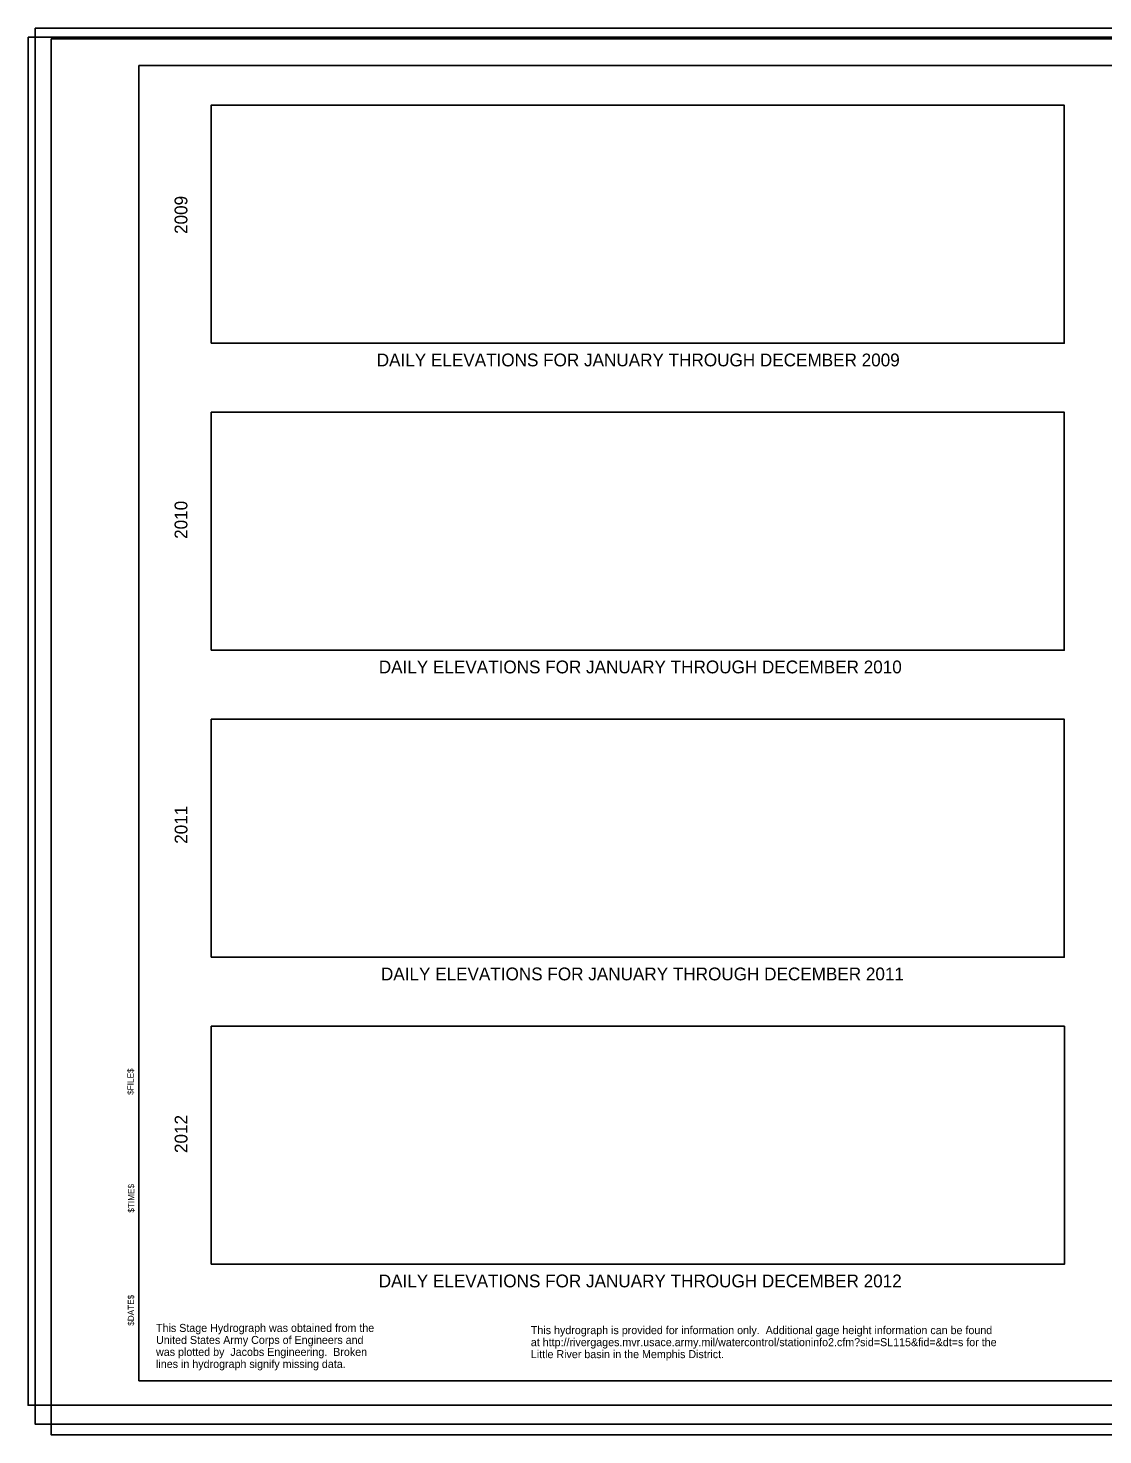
# Model space of a CAD drawing. Extents: x -1063117.9 to -1063075.9, y -253323.6 to -253301.6.
# Drawn here: x -1063117.89 to -1063101.09, y -253323.61 to -253301.63 of the extents above; entities that cross this region are included whole.
import ezdxf

# ---------------------------------------------------------------- set-up
doc = ezdxf.new("R2010")
doc.units = 0
for name, color, linetype in [('border', 7, 'Continuous'), ('Border 2660-Hwy18 - Level 62', 7, 'Continuous'), ('Border 2660-Hwy18 - Level 63', 7, 'Continuous'), ('Dimensions', 7, 'Continuous'), ('Level 62 PDF', 7, 'Continuous'), ('Text', 7, 'Continuous'), ('Title Text', 7, 'Continuous')]:
    doc.layers.add(name, color=color, linetype=linetype)

msp = doc.modelspace()

# ---------------------------------------------------------------- linework, layer by layer
at = {"layer": 'border'}
for p, q in [((-1063116.157, -253302.216), (-1063084.146, -253302.216)), ((-1063116.157, -253322.761), (-1063116.157, -253302.216)), ((-1063084.146, -253322.761), (-1063116.157, -253322.761))]:
    msp.add_line(p, q, dxfattribs=at)
at = {"layer": 'Border 2660-Hwy18 - Level 62'}
msp.add_lwpolyline([(-1063117.777, -253301.63), (-1063083.659, -253301.63), (-1063083.659, -253323.44), (-1063117.777, -253323.44)], close=True, dxfattribs=at)
at = {"layer": 'Border 2660-Hwy18 - Level 63'}
msp.add_lwpolyline([(-1063117.888, -253301.773), (-1063083.889, -253301.773), (-1063083.889, -253323.143), (-1063117.888, -253323.143)], close=True, dxfattribs=at)
at = {"layer": 'Dimensions'}
for points in [[(-1063115.028, -253306.552), (-1063101.694, -253306.552), (-1063101.694, -253302.836), (-1063115.028, -253302.836)], [(-1063115.027, -253311.348), (-1063101.694, -253311.348), (-1063101.694, -253307.632), (-1063115.027, -253307.632)], [(-1063115.027, -253316.144), (-1063101.694, -253316.144), (-1063101.694, -253312.428), (-1063115.027, -253312.428)], [(-1063115.027, -253320.94), (-1063101.693, -253320.94), (-1063101.693, -253317.224), (-1063115.027, -253317.224)]]:
    msp.add_lwpolyline(points, close=True, dxfattribs=at)
at = {"layer": 'Level 62 PDF'}
msp.add_lwpolyline([(-1063117.527, -253301.797), (-1063083.409, -253301.797), (-1063083.409, -253323.607), (-1063117.527, -253323.607)], close=True, dxfattribs=at)

# ---------------------------------------------------------------- texts
at = {"layer": 'border'}
for s, p in [('$FILE$', (-1063116.24, -253318.295)), ('$TIME$', (-1063116.23, -253320.136)), ('$DATE$', (-1063116.234, -253321.903))]:
    msp.add_text(s, height=0.096, rotation=89.9999, dxfattribs=at).set_placement(p)
at = {"layer": 'Text'}
for s, p in [('This Stage Hydrograph was obtained from the ', (-1063115.889, -253321.998)), ('This hydrograph is provided for information only.  Additional gage height information can be found ', (-1063110.031, -253322.033)), ('United States Army Corps of Engineers and ', (-1063115.889, -253322.186)), ('at http://rivergages.mvr.usace.army.mil/watercontrol/stationinfo2.cfm?sid=SL115&fid=&dt=s for the ', (-1063110.031, -253322.221)), ('was plotted by  Jacobs Engineering.  Broken ', (-1063115.889, -253322.373)), ('lines in hydrograph signify missing data.', (-1063115.889, -253322.561)), ('Little River basin in the Memphis District. ', (-1063110.031, -253322.408))]:
    msp.add_text(s, height=0.125, dxfattribs=at).set_placement(p)
at = {"layer": 'Title Text'}
for s, p in [('2009', (-1063115.399, -253304.846)), ('2010', (-1063115.399, -253309.61)), ('2011', (-1063115.398, -253314.373)), ('2012', (-1063115.398, -253319.204))]:
    msp.add_text(s, height=0.2, rotation=90, dxfattribs=at).set_placement(p)
for s, p in [(' DAILY ELEVATIONS FOR JANUARY THROUGH DECEMBER 2009 ', (-1063112.514, -253306.914)), (' DAILY ELEVATIONS FOR JANUARY THROUGH DECEMBER 2010 ', (-1063112.482, -253311.71)), (' DAILY ELEVATIONS FOR JANUARY THROUGH DECEMBER 2011 ', (-1063112.448, -253316.506)), (' DAILY ELEVATIONS FOR JANUARY THROUGH DECEMBER 2012 ', (-1063112.483, -253321.302))]:
    msp.add_text(s, height=0.2, dxfattribs=at).set_placement(p)

doc.saveas('drawing.dxf')
